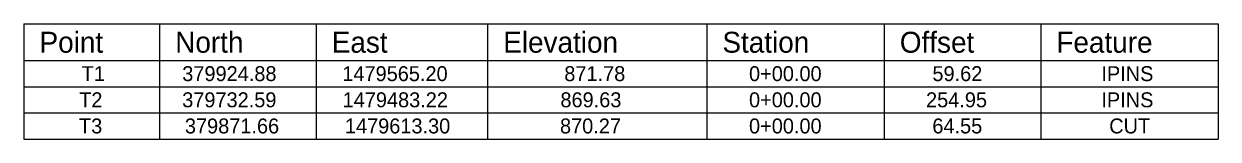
# Model space of a CAD drawing. Extents: x 1470334 to 1482043, y 378207 to 388330.
# Drawn here: x 1480006.6 to 1480407.1, y 380003.5 to 380042 of the extents above; entities that cross this region are included whole.
import ezdxf

# ---------------------------------------------------------------- set-up
doc = ezdxf.new("R2010")
doc.units = 0
doc.layers.add('Default', color=7, linetype='Continuous')

msp = doc.modelspace()

# ---------------------------------------------------------------- linework, layer by layer
at = {"layer": 'Default'}
for p, q in [((1480006.61, 380041.98), (1480407.11, 380041.98)), ((1480006.61, 380041.98), (1480006.61, 380003.48)), ((1480006.61, 380041.98), (1480407.11, 380041.98)), ((1480006.61, 380041.98), (1480006.61, 380003.48)), ((1480052.11, 380041.98), (1480052.11, 380003.48)), ((1480052.11, 380041.98), (1480052.11, 380003.48)), ((1480104.61, 380041.98), (1480104.61, 380003.48)), ((1480104.61, 380041.98), (1480104.61, 380003.48)), ((1480162.11, 380041.98), (1480162.11, 380003.48)), ((1480162.11, 380041.98), (1480162.11, 380003.48)), ((1480235.61, 380041.98), (1480235.61, 380003.48)), ((1480235.61, 380041.98), (1480235.61, 380003.48)), ((1480295.11, 380041.98), (1480295.11, 380003.48)), ((1480295.11, 380041.98), (1480295.11, 380003.48)), ((1480347.61, 380041.98), (1480347.61, 380003.48)), ((1480347.61, 380041.98), (1480347.61, 380003.48)), ((1480407.11, 380041.98), (1480407.11, 380003.48)), ((1480407.11, 380041.98), (1480407.11, 380003.48)), ((1480407.11, 380041.98), (1480407.11, 380003.48)), ((1480407.11, 380041.98), (1480407.11, 380003.48)), ((1480006.61, 380029.73), (1480407.11, 380029.73)), ((1480006.61, 380029.73), (1480407.11, 380029.73)), ((1480006.61, 380020.98), (1480407.11, 380020.98)), ((1480006.61, 380020.98), (1480407.11, 380020.98)), ((1480006.61, 380020.98), (1480407.11, 380020.98)), ((1480006.61, 380020.98), (1480407.11, 380020.98)), ((1480006.61, 380020.98), (1480407.11, 380020.98)), ((1480006.61, 380020.98), (1480407.11, 380020.98)), ((1480006.61, 380020.98), (1480407.11, 380020.98)), ((1480006.61, 380020.98), (1480407.11, 380020.98)), ((1480006.61, 380020.98), (1480407.11, 380020.98)), ((1480006.61, 380020.98), (1480407.11, 380020.98)), ((1480006.61, 380020.98), (1480407.11, 380020.98)), ((1480006.61, 380020.98), (1480407.11, 380020.98)), ((1480006.61, 380020.98), (1480407.11, 380020.98)), ((1480006.61, 380020.98), (1480407.11, 380020.98)), ((1480006.61, 380012.23), (1480407.11, 380012.23)), ((1480006.61, 380012.23), (1480407.11, 380012.23)), ((1480006.61, 380012.23), (1480407.11, 380012.23)), ((1480006.61, 380012.23), (1480407.11, 380012.23)), ((1480006.61, 380012.23), (1480407.11, 380012.23)), ((1480006.61, 380012.23), (1480407.11, 380012.23)), ((1480006.61, 380012.23), (1480407.11, 380012.23)), ((1480006.61, 380012.23), (1480407.11, 380012.23)), ((1480006.61, 380012.23), (1480407.11, 380012.23)), ((1480006.61, 380012.23), (1480407.11, 380012.23)), ((1480006.61, 380012.23), (1480407.11, 380012.23)), ((1480006.61, 380012.23), (1480407.11, 380012.23)), ((1480006.61, 380012.23), (1480407.11, 380012.23)), ((1480006.61, 380012.23), (1480407.11, 380012.23)), ((1480006.61, 380003.48), (1480407.11, 380003.48)), ((1480006.61, 380003.48), (1480407.11, 380003.48)), ((1480006.61, 380003.48), (1480407.11, 380003.48)), ((1480006.61, 380003.48), (1480407.11, 380003.48)), ((1480006.61, 380003.48), (1480407.11, 380003.48)), ((1480006.61, 380003.48), (1480407.11, 380003.48)), ((1480006.61, 380003.48), (1480407.11, 380003.48)), ((1480006.61, 380003.48), (1480407.11, 380003.48)), ((1480006.61, 380003.48), (1480407.11, 380003.48)), ((1480006.61, 380003.48), (1480407.11, 380003.48)), ((1480006.61, 380003.48), (1480407.11, 380003.48)), ((1480006.61, 380003.48), (1480407.11, 380003.48)), ((1480006.61, 380003.48), (1480407.11, 380003.48)), ((1480006.61, 380003.48), (1480407.11, 380003.48))]:
    msp.add_line(p, q, dxfattribs=at)

# ---------------------------------------------------------------- texts
for s, height, p in [('Point', 7, (1480011.86, 380032.36)), ('Point', 7, (1480011.86, 380032.36)), ('North', 7, (1480057.36, 380032.36)), ('North', 7, (1480057.36, 380032.36)), ('East', 7, (1480109.86, 380032.36)), ('East', 7, (1480109.86, 380032.36)), ('Elevation', 7, (1480167.36, 380032.36)), ('Elevation', 7, (1480167.36, 380032.36)), ('Station', 7, (1480240.86, 380032.36)), ('Station', 7, (1480240.86, 380032.36)), ('Offset', 7, (1480300.36, 380032.36)), ('Offset', 7, (1480300.36, 380032.36)), ('Feature', 7, (1480352.86, 380032.36)), ('Feature', 7, (1480352.86, 380032.36)), ('T1', 5, (1480025.98, 380022.86)), ('T1', 5, (1480025.98, 380022.86)), ('379924.88', 5, (1480059.72, 380022.86)), ('379924.88', 5, (1480059.72, 380022.86)), ('1479565.20', 5, (1480113.4, 380022.86)), ('1479565.20', 5, (1480113.4, 380022.86)), ('871.78', 5, (1480187.84, 380022.86)), ('871.78', 5, (1480187.84, 380022.86)), ('0+00.00', 5, (1480249.79, 380022.86)), ('0+00.00', 5, (1480249.79, 380022.86)), ('59.62', 5, (1480311.3, 380022.86)), ('59.62', 5, (1480311.3, 380022.86)), ('IPINS', 5, (1480367.95, 380022.86)), ('IPINS', 5, (1480367.95, 380022.86)), ('T2', 5, (1480025.15, 380014.11)), ('T2', 5, (1480025.15, 380014.11)), ('379732.59', 5, (1480059.7, 380014.11)), ('379732.59', 5, (1480059.7, 380014.11)), ('1479483.22', 5, (1480113.5, 380014.11)), ('1479483.22', 5, (1480113.5, 380014.11)), ('869.63', 5, (1480186.54, 380014.11)), ('869.63', 5, (1480186.54, 380014.11)), ('0+00.00', 5, (1480249.79, 380014.11)), ('0+00.00', 5, (1480249.79, 380014.11)), ('254.95', 5, (1480309.16, 380014.11)), ('254.95', 5, (1480309.16, 380014.11)), ('IPINS', 5, (1480367.95, 380014.11)), ('IPINS', 5, (1480367.95, 380014.11)), ('T3', 5, (1480025.09, 380005.36)), ('T3', 5, (1480025.09, 380005.36)), ('379871.66', 5, (1480060.61, 380005.36)), ('379871.66', 5, (1480060.61, 380005.36)), ('1479613.30', 5, (1480114.27, 380005.36)), ('1479613.30', 5, (1480114.27, 380005.36)), ('870.27', 5, (1480186.4, 380005.36)), ('870.27', 5, (1480186.4, 380005.36)), ('0+00.00', 5, (1480249.79, 380005.36)), ('0+00.00', 5, (1480249.79, 380005.36)), ('64.55', 5, (1480311.28, 380005.36)), ('64.55', 5, (1480311.28, 380005.36)), ('CUT', 5, (1480370.59, 380005.36)), ('CUT', 5, (1480370.59, 380005.36))]:
    msp.add_text(s, height=height, dxfattribs=at).set_placement(p)

doc.saveas('drawing.dxf')
